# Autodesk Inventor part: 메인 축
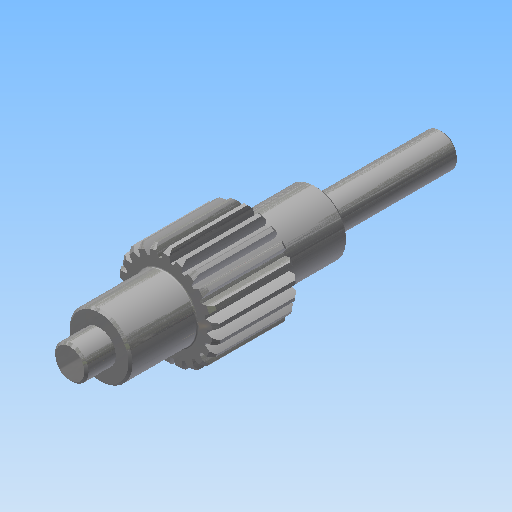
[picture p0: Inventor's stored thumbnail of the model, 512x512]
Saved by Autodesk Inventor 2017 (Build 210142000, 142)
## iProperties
Created: 2016-02
Part Number: 메인 축
Material: 강철, 연강
Document SubType Name: Modeling
Categories: <?xml version="1.0" encoding="UTF-16"?> <MemberInstance><Categories><FamilyTemplate><FamilyTemplateParameter ValueType="xs:double" Id="1" ObjectReferenceKey="da
Density: 7.86 g/cm^3
Appearance: 강철
CustomPartVersion: 1
Author: mdu
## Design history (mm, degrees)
sketch "Sketch1"
  geometry: C1 r 12 at (0, 0)
  constraints: 1 centre point
  dimensions: "d0" = 24 diameter of C1 (= da_da)
extrude "Extrusion1" new body sketch "Sketch1" distance "d1" = 20 (= da_b); taper "d2" = 0 deg
workplane "Work Plane2"
feature "피치 지름" dims "d4" = 10, "d5" = 0
workplane "Work Plane8"
workplane "Work Plane9"
chamfer "모따기1" distance "d49" = 1; stored, may be unused: second distance "d50" = 2, angle "d51" = 45 deg
sketch "스케치3"
  geometry: C1 r 7.5 at (0, 0); 1 further point
  constraints: 1 centre point, 1 coincident
  dimensions: "d52" = 15 diameter of C1
extrude "돌출2" join sketch "스케치3" distance "d53" = 16; taper "d54" = 0 deg
sketch "스케치4"
  geometry: C1 r 4 at (0, 0); 1 further point
  constraints: 1 centre point, 1 coincident
  dimensions: "d55" = 8 diameter of C1
extrude "돌출3" join sketch "스케치4" distance "d56" = 7; taper "d57" = 0 deg
sketch "스케치5"
  geometry: C1 r 7.5 at (0, 0) reference; C2 r 7.5 at (0, 0) reference; 1 further point
extrude "돌출4" join sketch "스케치5" distance "d62" = 16; taper "d63" = 0 deg
sketch "스케치6"
  geometry: C1 r 4 at (0, 0); 1 further point
  constraints: 1 centre point, 1 coincident
  dimensions: "d64" = 8 diameter of C1
extrude "돌출5" join sketch "스케치6" distance "d65" = 30; taper "d66" = 0 deg
chamfer "모따기2" distance "d58" = 0.5; stored, may be unused: second distance "d59" = 2, angle "d60" = 45 deg
fillet "모깎기1" dims "d61" = 0.3
feature "스퍼 기어" dims "d34" = 1.428 (computed from da_z), "da_b" = 20, "da_d" = 22, "da_aw" = 31, "da_da" = 24, "da_df" = 19.5, "da_dw" = 22, angle "da_beta" = 0 deg, "da_lefttooth" = 0, "da_righttooth" = 0
body "Solid1"
sketch "Sketch2"
  geometry: C1 r 12 at (0, 0) reference; C2 r 11 at (0, 0)
  constraints: 1 centre point, 1 coincident
  dimensions: "d3" = 22 diameter of C2 (= da_dw)
body "Srf1"
node "투영된 루프1"
other parameters: "d16" = 31 (= da_aw), "d17" = 0, "d39" = 0, "d41" = 0, "d43" = 31 (= da_aw), "d46" = 31 (= da_aw), "d47" = 0, "d48" = 0
